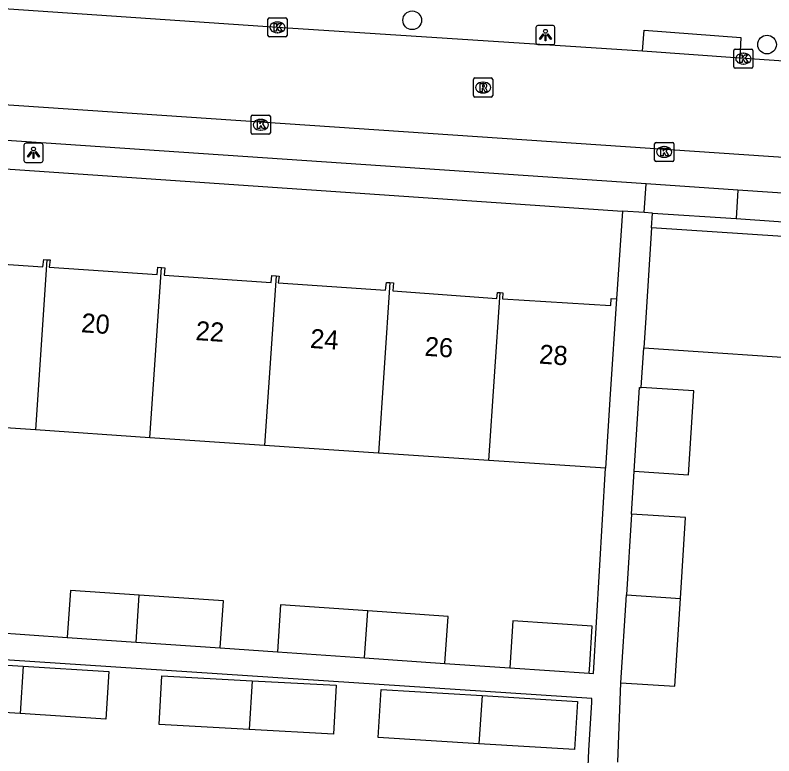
# Model space of a CAD drawing. Extents: x 161848 to 162726, y 385382 to 386521.
# Drawn here: x 162177.96 to 162217.68, y 386183.18 to 386221.96 of the extents above; entities that cross this region are included whole.
import ezdxf

# ---------------------------------------------------------------- set-up
doc = ezdxf.new("R2010")
doc.units = 0
for name, color, linetype in [('IMGEO_Boom', 7, 'Continuous'), ('IMGEO_Kolk', 7, 'Continuous'), ('IMGEO_Lichtpunt', 7, 'Continuous'), ('IMGEO_Pand', 7, 'Continuous'), ('IMGEO_Pand_nummerreeks', 7, 'Continuous'), ('IMGEO_Rijbaan_lokaal_open', 7, 'Continuous'), ('IMGEO_Rioolput', 7, 'Continuous'), ('IMGEO_Voetpad_open', 7, 'Continuous')]:
    doc.layers.add(name, color=color, linetype=linetype)

msp = doc.modelspace()

# ---------------------------------------------------------------- linework, layer by layer
at = {"layer": 'IMGEO_Boom'}
for centre in [(162198.745, 386221.693), (162217.324, 386220.421)]:
    msp.add_circle(centre, 0.489, dxfattribs=at)
at = {"layer": 'IMGEO_Kolk'}
for p, q in [((162191.19, 386220.897), (162191.19, 386221.749)), ((162191.265, 386221.823), (162192.117, 386221.823)), ((162192.191, 386221.749), (162192.191, 386220.897)), ((162191.678, 386221.603), (162191.703, 386221.603)), ((162191.701, 386221.043), (162191.676, 386221.043)), ((162192.117, 386220.823), (162191.265, 386220.823)), ((162215.587, 386219.257), (162215.587, 386220.109)), ((162215.662, 386220.183), (162216.514, 386220.183)), ((162216.588, 386220.109), (162216.588, 386219.257)), ((162216.075, 386219.963), (162216.1, 386219.963)), ((162216.098, 386219.403), (162216.073, 386219.403)), ((162216.514, 386219.183), (162215.662, 386219.183)), ((162190.316, 386215.797), (162190.316, 386216.649)), ((162190.391, 386216.723), (162191.243, 386216.723)), ((162191.317, 386216.649), (162191.317, 386215.797)), ((162190.804, 386216.503), (162190.829, 386216.503)), ((162191.243, 386215.723), (162190.391, 386215.723)), ((162190.827, 386215.943), (162190.802, 386215.943)), ((162211.44, 386214.371), (162211.44, 386215.223)), ((162211.515, 386215.297), (162212.367, 386215.297)), ((162211.928, 386215.077), (162211.953, 386215.077)), ((162212.441, 386215.223), (162212.441, 386214.371)), ((162212.367, 386214.297), (162211.515, 386214.297)), ((162211.951, 386214.517), (162211.926, 386214.517))]:
    msp.add_line(p, q, dxfattribs=at)
for points in [[(162191.19, 386220.897), (162191.19, 386221.749)], [(162191.265, 386221.823), (162192.117, 386221.823)], [(162192.191, 386221.749), (162192.191, 386220.897)], [(162191.511, 386221.523), (162191.634, 386221.523), (162191.634, 386221.372), (162191.764, 386221.523), (162191.928, 386221.523), (162191.782, 386221.372), (162191.935, 386221.123), (162191.783, 386221.123), (162191.698, 386221.287), (162191.634, 386221.22), (162191.634, 386221.123), (162191.511, 386221.123), (162191.511, 386221.523)], [(162192.117, 386220.823), (162191.265, 386220.823)], [(162215.587, 386219.257), (162215.587, 386220.109)], [(162215.662, 386220.183), (162216.514, 386220.183)], [(162216.588, 386220.109), (162216.588, 386219.257)], [(162215.908, 386219.883), (162216.031, 386219.883), (162216.031, 386219.732), (162216.161, 386219.883), (162216.325, 386219.883), (162216.179, 386219.732), (162216.332, 386219.483), (162216.18, 386219.483), (162216.095, 386219.647), (162216.031, 386219.58), (162216.031, 386219.483), (162215.908, 386219.483), (162215.908, 386219.883)], [(162216.514, 386219.183), (162215.662, 386219.183)], [(162190.316, 386215.797), (162190.316, 386216.649)], [(162190.391, 386216.723), (162191.243, 386216.723)], [(162191.317, 386216.649), (162191.317, 386215.797)], [(162190.637, 386216.423), (162190.76, 386216.423), (162190.76, 386216.272), (162190.89, 386216.423), (162191.054, 386216.423), (162190.908, 386216.272), (162191.061, 386216.023), (162190.909, 386216.023), (162190.824, 386216.187), (162190.76, 386216.12), (162190.76, 386216.023), (162190.637, 386216.023), (162190.637, 386216.423)], [(162191.243, 386215.723), (162190.391, 386215.723)], [(162211.44, 386214.371), (162211.44, 386215.223)], [(162211.515, 386215.297), (162212.367, 386215.297)], [(162211.761, 386214.997), (162211.884, 386214.997), (162211.884, 386214.846), (162212.014, 386214.997), (162212.178, 386214.997), (162212.032, 386214.846), (162212.185, 386214.597), (162212.033, 386214.597), (162211.948, 386214.761), (162211.884, 386214.694), (162211.884, 386214.597), (162211.761, 386214.597), (162211.761, 386214.997)], [(162212.441, 386215.223), (162212.441, 386214.371)], [(162212.367, 386214.297), (162211.515, 386214.297)]]:
    msp.add_lwpolyline(points, dxfattribs=at)
for centre, start, end in [((162191.267, 386221.747), 91.552, 178.448), ((162191.267, 386221.747), 91.552, 178.448), ((162192.115, 386221.747), 1.552, 88.448), ((162192.115, 386221.747), 1.552, 88.448), ((162191.267, 386220.899), 181.552, 268.448), ((162191.267, 386220.899), 181.552, 268.448), ((162192.115, 386220.899), 271.552, 358.448), ((162192.115, 386220.899), 271.552, 358.448), ((162215.664, 386220.107), 91.552, 178.448), ((162215.664, 386220.107), 91.552, 178.448), ((162216.512, 386220.107), 1.552, 88.448), ((162216.512, 386220.107), 1.552, 88.448), ((162215.664, 386219.259), 181.552, 268.448), ((162215.664, 386219.259), 181.552, 268.448), ((162216.512, 386219.259), 271.552, 358.448), ((162216.512, 386219.259), 271.552, 358.448), ((162190.393, 386216.647), 91.552, 178.448), ((162190.393, 386216.647), 91.552, 178.448), ((162191.241, 386216.647), 1.552, 88.448), ((162191.241, 386216.647), 1.552, 88.448), ((162190.393, 386215.799), 181.552, 268.448), ((162190.393, 386215.799), 181.552, 268.448), ((162191.241, 386215.799), 271.552, 358.448), ((162191.241, 386215.799), 271.552, 358.448), ((162211.517, 386215.221), 91.552, 178.448), ((162211.517, 386215.221), 91.552, 178.448), ((162212.365, 386215.221), 1.552, 88.448), ((162212.365, 386215.221), 1.552, 88.448), ((162211.517, 386214.373), 181.552, 268.448), ((162211.517, 386214.373), 181.552, 268.448), ((162212.365, 386214.373), 271.552, 358.448), ((162212.365, 386214.373), 271.552, 358.448)]:
    msp.add_arc(centre, 0.0765, start, end, dxfattribs=at)
for centre, major_axis, ratio, start_param, end_param in [((162191.677, 386221.323), (-0.387, 0.002), 0.722429, 4.712389, 7.853982), ((162191.702, 386221.323), (-0.39, 0.002), 0.717154, 1.570796, 4.712389), ((162216.074, 386219.683), (-0.387, 0.002), 0.722429, 4.712389, 7.853982), ((162216.099, 386219.683), (-0.39, 0.002), 0.717154, 1.570796, 4.712389), ((162190.803, 386216.223), (-0.387, 0.002), 0.722429, 4.712389, 7.853982), ((162190.828, 386216.223), (-0.39, 0.002), 0.717154, 1.570796, 4.712389), ((162211.927, 386214.797), (-0.387, 0.002), 0.722429, 4.712389, 7.853982), ((162211.952, 386214.797), (-0.39, 0.002), 0.717154, 1.570796, 4.712389)]:
    msp.add_ellipse(centre, major_axis=major_axis, ratio=ratio, start_param=start_param, end_param=end_param, dxfattribs=at)
at = {"layer": 'IMGEO_Lichtpunt'}
for p, q in [((162205.225, 386221.32), (162205.225, 386220.513)), ((162205.225, 386221.32), (162205.225, 386220.513)), ((162206.127, 386221.415), (162205.319, 386221.415)), ((162206.127, 386221.415), (162205.319, 386221.415)), ((162206.221, 386220.513), (162206.221, 386221.32)), ((162206.221, 386220.513), (162206.221, 386221.32)), ((162205.319, 386220.419), (162206.127, 386220.419)), ((162205.319, 386220.419), (162206.127, 386220.419)), ((162178.417, 386215.156), (162178.417, 386214.349)), ((162178.417, 386215.156), (162178.417, 386214.349)), ((162179.319, 386215.251), (162178.511, 386215.251)), ((162179.319, 386215.251), (162178.511, 386215.251)), ((162179.413, 386214.349), (162179.413, 386215.156)), ((162179.413, 386214.349), (162179.413, 386215.156)), ((162178.511, 386214.255), (162179.319, 386214.255)), ((162178.511, 386214.255), (162179.319, 386214.255))]:
    msp.add_line(p, q, dxfattribs=at)
for points in [[(162205.599, 386220.984), (162205.638, 386220.956), (162205.45, 386220.694), (162205.412, 386220.721), (162205.599, 386220.984)], [(162205.701, 386220.936), (162205.748, 386220.936), (162205.748, 386220.614), (162205.701, 386220.614), (162205.701, 386220.936)], [(162205.811, 386220.956), (162205.849, 386220.983), (162206.036, 386220.721), (162205.997, 386220.693), (162205.811, 386220.956)], [(162178.791, 386214.82), (162178.83, 386214.792), (162178.642, 386214.53), (162178.604, 386214.557), (162178.791, 386214.82)], [(162178.893, 386214.772), (162178.94, 386214.772), (162178.94, 386214.45), (162178.893, 386214.45), (162178.893, 386214.772)], [(162179.003, 386214.792), (162179.041, 386214.819), (162179.228, 386214.557), (162179.189, 386214.529), (162179.003, 386214.792)]]:
    msp.add_lwpolyline(points, dxfattribs=at)
for centre in [(162205.724, 386221.118), (162178.916, 386214.954)]:
    msp.add_circle(centre, 0.0994, dxfattribs=at)
for centre, start, end in [((162205.319, 386221.32), 90, 180), ((162205.319, 386221.32), 90, 180), ((162206.127, 386221.32), 0, 90), ((162206.127, 386221.32), 0, 90), ((162205.319, 386220.513), 180, 270), ((162205.319, 386220.513), 180, 270), ((162206.127, 386220.513), 270, 0), ((162206.127, 386220.513), 270, 360), ((162178.511, 386215.156), 90, 180), ((162178.511, 386215.156), 90, 180), ((162179.319, 386215.156), 0, 90), ((162179.319, 386215.156), 0, 90), ((162178.511, 386214.349), 180, 270), ((162178.511, 386214.349), 180, 270), ((162179.319, 386214.349), 270, 0), ((162179.319, 386214.349), 270, 360)]:
    msp.add_arc(centre, 0.0946, start, end, dxfattribs=at)
at = {"layer": 'IMGEO_Pand'}
for points in [[(162211.283, 386210.833), (162210.953, 386205.844), (162210.867, 386204.545)], [(162229.385, 386203.63), (162227.948, 386209.731), (162211.283, 386210.833)], [(162173.618, 386209.532), (162173.791, 386209.52), (162173.755, 386209.173), (162179.404, 386208.786), (162179.456, 386209.165), (162179.622, 386209.154)], [(162179.622, 386209.154), (162179.018, 386200.243)], [(162179.622, 386209.154), (162179.79, 386209.143), (162179.741, 386208.763), (162185.389, 386208.377), (162185.434, 386208.761), (162185.612, 386208.749)], [(162185.009, 386199.84), (162185.612, 386208.749)], [(162185.612, 386208.749), (162185.788, 386208.737), (162185.75, 386208.352), (162191.362, 386207.968), (162191.4, 386208.328), (162191.616, 386208.313)], [(162191.616, 386208.313), (162191.014, 386199.436)], [(162191.616, 386208.313), (162191.783, 386208.302), (162191.734, 386207.943), (162197.346, 386207.559), (162197.396, 386207.972), (162197.58, 386207.96)], [(162197.58, 386207.96), (162196.976, 386199.035)], [(162197.58, 386207.96), (162197.766, 386207.947), (162197.732, 386207.532), (162203.185, 386207.132), (162203.205, 386207.448), (162203.35, 386207.438)], [(162202.754, 386198.646), (162203.35, 386207.438)], [(162203.35, 386207.438), (162203.494, 386207.429), (162203.474, 386207.117), (162209.14, 386206.752), (162209.163, 386207.118), (162209.435, 386207.101)], [(162209.435, 386207.101), (162209.114, 386202.112), (162208.865, 386198.235)], [(162210.867, 386204.545), (162220.703, 386203.887)], [(162210.374, 386198.082), (162210.653, 386202.473), (162210.735, 386202.468)], [(162210.374, 386198.082), (162213.205, 386197.893), (162213.484, 386202.293), (162210.735, 386202.468)], [(162179.018, 386200.243), (162173.016, 386200.646)], [(162185.009, 386199.84), (162179.018, 386200.243)], [(162191.014, 386199.436), (162185.009, 386199.84)], [(162196.976, 386199.035), (162191.014, 386199.436)], [(162202.754, 386198.646), (162196.976, 386199.035)], [(162208.865, 386198.235), (162202.754, 386198.646)], [(162210.231, 386195.835), (162209.963, 386191.614)], [(162212.794, 386191.426), (162213.063, 386195.655), (162210.231, 386195.835)], [(162184.451, 386191.596), (162180.851, 386191.843), (162180.681, 386189.382)], [(162184.284, 386189.134), (162184.451, 386191.596)], [(162188.683, 386188.832), (162188.863, 386191.293), (162184.451, 386191.596)], [(162209.67, 386187.012), (162209.963, 386191.614)], [(162209.963, 386191.614), (162212.794, 386191.426)], [(162209.67, 386187.012), (162212.502, 386186.832), (162212.794, 386191.426)], [(162196.417, 386190.774), (162191.853, 386191.088), (162191.699, 386188.625)], [(162196.25, 386188.313), (162196.417, 386190.774)], [(162200.456, 386188.024), (162200.623, 386190.485), (162196.417, 386190.774)], [(162208.018, 386187.505), (162208.046, 386187.942), (162208.174, 386189.967), (162204.022, 386190.252), (162203.855, 386187.791)], [(162180.681, 386189.382), (162184.284, 386189.134)], [(162184.284, 386189.134), (162188.683, 386188.832)], [(162191.699, 386188.625), (162196.25, 386188.313)], [(162196.25, 386188.313), (162200.456, 386188.024)], [(162178.211, 386185.39), (162174.274, 386185.636), (162174.429, 386188.119), (162178.377, 386187.872)], [(162178.377, 386187.872), (162182.853, 386187.592), (162182.698, 386185.11), (162178.211, 386185.39)], [(162178.377, 386187.872), (162178.211, 386185.39)], [(162203.855, 386187.791), (162208.018, 386187.505)], [(162190.201, 386184.561), (162185.498, 386184.814), (162185.635, 386187.369), (162190.371, 386187.114)], [(162190.371, 386187.114), (162194.761, 386186.877), (162194.624, 386184.323), (162190.201, 386184.561)], [(162190.371, 386187.114), (162190.201, 386184.561)], [(162202.235, 386183.818), (162196.97, 386184.137), (162197.122, 386186.655), (162202.402, 386186.335)], [(162202.402, 386186.335), (162207.402, 386186.033), (162207.25, 386183.515), (162202.235, 386183.818)], [(162202.402, 386186.335), (162202.235, 386183.818)]]:
    msp.add_lwpolyline(points, dxfattribs=at)
at = {"layer": 'IMGEO_Rijbaan_lokaal_open'}
for points in [[(162210.81, 386220.084), (162191.691, 386221.323), (162124.924, 386225.884)], [(162127.244, 386220.666), (162233.934, 386213.458)], [(162215.893, 386219.705), (162210.81, 386220.084)], [(162236.622, 386218.288), (162215.893, 386219.705)]]:
    msp.add_lwpolyline(points, dxfattribs=at)
at = {"layer": 'IMGEO_Rioolput'}
for p, q in [((162201.958, 386217.746), (162201.958, 386218.598)), ((162202.033, 386218.672), (162202.885, 386218.672)), ((162202.959, 386218.598), (162202.959, 386217.746)), ((162202.446, 386218.452), (162202.471, 386218.452)), ((162202.469, 386217.892), (162202.444, 386217.892)), ((162202.885, 386217.672), (162202.033, 386217.672))]:
    msp.add_line(p, q, dxfattribs=at)
for points in [[(162201.958, 386217.746), (162201.958, 386218.598)], [(162202.033, 386218.672), (162202.885, 386218.672)], [(162202.959, 386218.598), (162202.959, 386217.746)], [(162202.547, 386218.37), (162202.295, 386218.372), (162202.295, 386217.972)], [(162202.295, 386217.972), (162202.419, 386217.972), (162202.419, 386218.134), (162202.43, 386218.134)], [(162202.473, 386218.291), (162202.419, 386218.291), (162202.419, 386218.21)], [(162202.419, 386218.21), (162202.471, 386218.21)], [(162202.477, 386218.105), (162202.548, 386217.972), (162202.688, 386217.972), (162202.623, 386218.098)], [(162202.885, 386217.672), (162202.033, 386217.672)]]:
    msp.add_lwpolyline(points, dxfattribs=at)
for centre, radius, start, end in [((162202.035, 386218.596), 0.0765, 91.552, 178.448), ((162202.035, 386218.596), 0.0765, 91.552, 178.448), ((162202.883, 386218.596), 0.0765, 1.552, 88.448), ((162202.883, 386218.596), 0.0765, 1.552, 88.448), ((162202.429, 386218.081), 0.0533, 26.0293, 88.6989), ((162202.455, 386218.399), 0.19, 274.7715, 282.9687), ((162202.479, 386218.195), 0.0964, 77.0061, 93.1865), ((162202.493, 386218.252), 0.0378, 276.6634, 79.6772), ((162202.546, 386218.26), 0.109, 350.3612, 89.416), ((162202.544, 386218.26), 0.112, 277.5842, 350.9817), ((162202.528, 386218.045), 0.108, 29.5134, 73.7905), ((162202.035, 386217.748), 0.0765, 181.552, 268.448), ((162202.035, 386217.748), 0.0765, 181.552, 268.448), ((162202.883, 386217.748), 0.0765, 271.552, 358.448), ((162202.883, 386217.748), 0.0765, 271.552, 358.448)]:
    msp.add_arc(centre, radius, start, end, dxfattribs=at)
for centre, major_axis, ratio, start_param, end_param in [((162202.445, 386218.172), (-0.387, 0.002), 0.722429, 4.712389, 7.853982), ((162202.47, 386218.172), (-0.39, 0.002), 0.717154, 1.570796, 4.712389)]:
    msp.add_ellipse(centre, major_axis=major_axis, ratio=ratio, start_param=start_param, end_param=end_param, dxfattribs=at)
at = {"layer": 'IMGEO_Voetpad_open'}
for points in [[(162210.81, 386220.084), (162210.883, 386221.174), (162215.957, 386220.785), (162215.893, 386219.705)], [(162210.992, 386213.124), (162135.002, 386218.276), (162129.835, 386218.561)], [(162125.759, 386217.317), (162169.273, 386214.472), (162209.75, 386211.703)], [(162210.89, 386211.625), (162210.992, 386213.124)], [(162215.792, 386212.793), (162210.992, 386213.124)], [(162215.792, 386212.793), (162215.708, 386211.318)], [(162230.846, 386211.782), (162215.792, 386212.793)], [(162209.75, 386211.703), (162209.435, 386207.101)], [(162210.89, 386211.625), (162209.75, 386211.703)], [(162211.332, 386211.597), (162210.89, 386211.625)], [(162211.283, 386210.833), (162211.332, 386211.597)], [(162211.332, 386211.597), (162215.708, 386211.318)], [(162215.708, 386211.318), (162234.925, 386209.956), (162236.034, 386209.677), (162236.872, 386209.172), (162237.513, 386208.343), (162237.841, 386207.442)], [(162210.735, 386202.468), (162210.867, 386204.545)], [(162208.018, 386187.505), (162208.234, 386187.49), (162208.865, 386198.235)], [(162210.231, 386195.835), (162210.374, 386198.082)], [(162207.65, 386175.158), (162207.991, 386183.47), (162208.143, 386185.988), (162208.155, 386186.179), (162130.187, 386191.319)], [(162176.722, 386189.653), (162180.681, 386189.382)], [(162188.683, 386188.832), (162191.699, 386188.625)], [(162200.456, 386188.024), (162203.855, 386187.791)], [(162209.507, 386182.85), (162209.67, 386187.012)]]:
    msp.add_lwpolyline(points, dxfattribs=at)

# ---------------------------------------------------------------- texts
at = {"layer": 'IMGEO_Pand_nummerreeks'}
for s, p in [('20', (162181.39, 386205.363)), ('22', (162187.379, 386204.953)), ('24', (162193.376, 386204.542)), ('26', (162199.371, 386204.132)), ('28', (162205.369, 386203.722))]:
    msp.add_text(s, height=1, rotation=356.0864, dxfattribs=at).set_placement(p)

doc.saveas('drawing.dxf')
